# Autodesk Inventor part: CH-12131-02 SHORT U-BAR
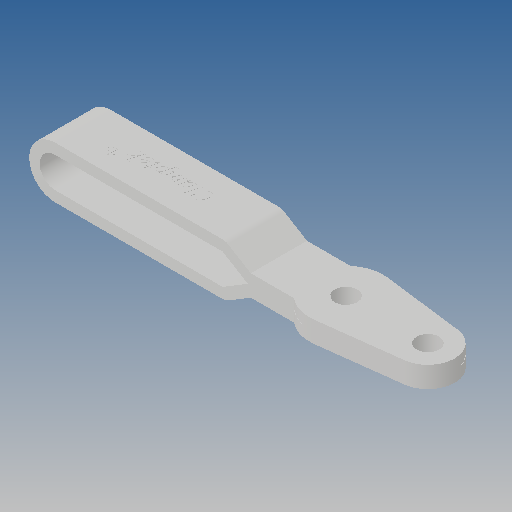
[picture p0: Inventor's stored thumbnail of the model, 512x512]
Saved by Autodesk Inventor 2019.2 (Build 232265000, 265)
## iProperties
Created: 2012-09
Part Number: CH-12131-02 SHORT U-BAR
Material: Ogólny
Document SubType Name: Modeling
Designer: CADENGINEERING4
Density: 1 g/cm^3
Appearance: Domyślna
Author: CADENGINEERING4
Revision Number: ÈÎºÎ
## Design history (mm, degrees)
feature "ÇÐ³ý-À­Éì2"
feature "ÇÐ³ý-À­Éì6"
node "Bryła1"
node "Bryła2"
